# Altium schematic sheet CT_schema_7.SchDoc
size 255 x 245 mm
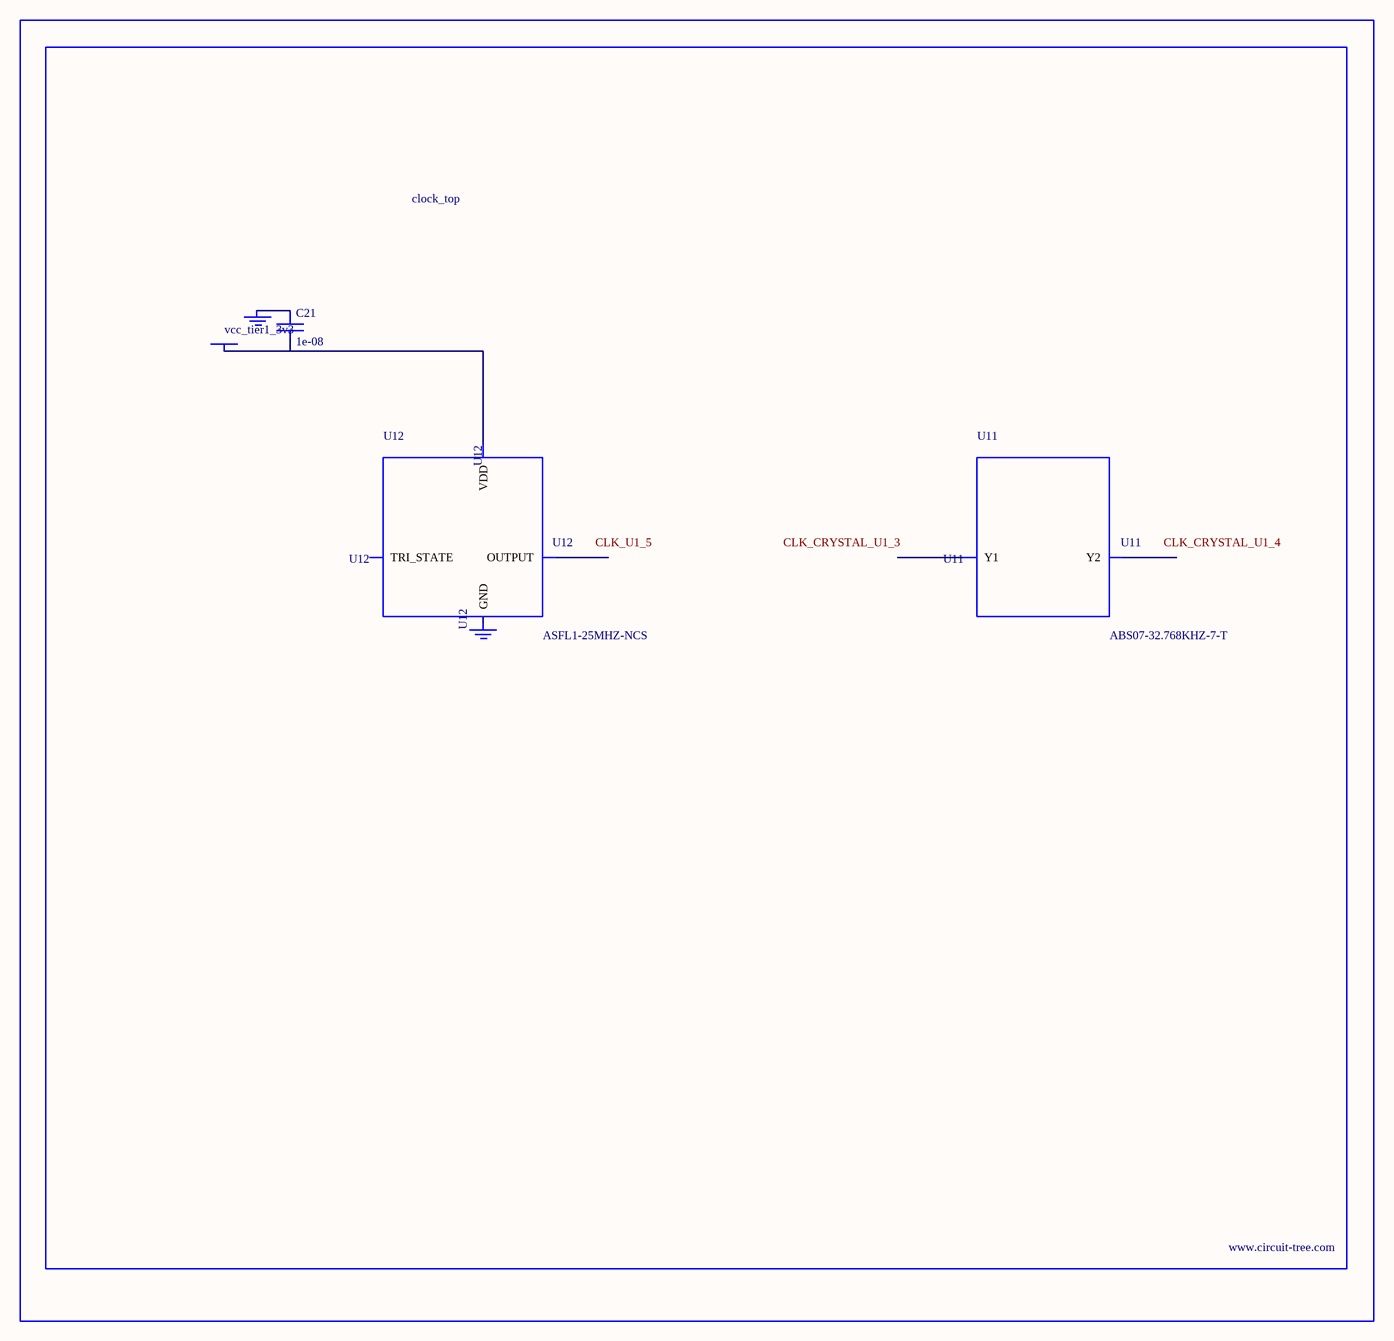
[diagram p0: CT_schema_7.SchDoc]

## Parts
BORDER6  (no value)
C21  1e-08  [C0402]
GND_INSTANCE_6_0  (no value)
GND_INSTANCE_6_1  (no value)
POWER_INSTANCE_6_0  vcc_tier1_3v3
U11  ABS07-32.768KHZ-7-T  [ABS07-32.768KHZ-7-T]
U12  ASFL1-25MHZ-NCS  [ASFL1]

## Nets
NetC21_1: C21.1 GND_INSTANCE_6_0.0(GND)
NetC21_2: C21.2 POWER_INSTANCE_6_0.0(PWR) U12.4(VDD)

Not connected (* = marked no-connect by the designer): GND_INSTANCE_6_1 0(GND); U11 1(Y1) 2(Y2); U12 1(TRI_STATE) 2(GND) 3(OUTPUT)

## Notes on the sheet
- Labels drawn without touching a wire or pin: CLK_CRYSTAL_U1_3, CLK_CRYSTAL_U1_4, CLK_U1_5

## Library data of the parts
BORDER6 = BORDER_PAGE6
C21 = C0402C103K3RAC
GND_INSTANCE_6_0 GND_INSTANCE_6_1 = GND
POWER_INSTANCE_6_0 = PWR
